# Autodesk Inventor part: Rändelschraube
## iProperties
Created: 2007-11
Part Number: Rändelschraube
Document SubType Name: Modeling
Designer: Benno
Manufacturer: Standard
Standards Organization: Custom
Material: Aluminium - 6061
Author: Benno
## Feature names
1. Drehung1 [Revolution]
2. Fase1 [Chamfer]
3. Fase2 [Chamfer]
